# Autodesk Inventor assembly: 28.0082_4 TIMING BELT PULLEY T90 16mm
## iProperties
Created: 2007-04
Part Number: 28.0082_4 TIMING BELT PULLEY T90 16mm
Document SubType Name: Assembly
Designer: Andy Moles
Author: Andy Moles
